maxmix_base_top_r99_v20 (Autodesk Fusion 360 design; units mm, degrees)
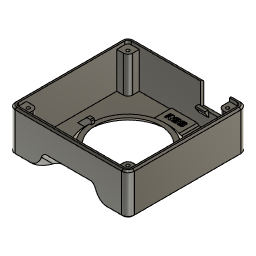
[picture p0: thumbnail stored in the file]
sketch "Sketch1" plane through (0, 0, 0) normal (0, 0, 1) x axis (1, 0, 0)
  line L1 (33, 37) -> (-33, 37)
  line L2 (37, -33) -> (37, 33)
  line L3 (-33, -37) -> (33, -37)
  line L4 (-37, 33) -> (-37, -33)
  line L5 (33, 35) -> (-33, 35)
  line L6 (35, -33) -> (35, 33)
  line L7 (-33, -35) -> (33, -35)
  line L8 (-35, 33) -> (-35, -33)
  line L9 (33, -33) -> (-33, 33)
  line L10 (-33, -33) -> (33, 33)
  arc A1 centre (-33, 33) radius 4 clockwise from (-37, 33) to (-33, 37)
  arc A2 centre (-33, -33) radius 4 clockwise from (-33, -37) to (-37, -33)
  arc A3 centre (33, -33) radius 4 clockwise from (37, -33) to (33, -37)
  arc A4 centre (33, 33) radius 4 clockwise from (33, 37) to (37, 33)
  arc A5 centre (-33, 33) radius 2 clockwise from (-35, 33) to (-33, 35)
  arc A6 centre (-33, -33) radius 2 clockwise from (-33, -35) to (-35, -33)
  arc A7 centre (33, -33) radius 2 clockwise from (35, -33) to (33, -35)
  arc A8 centre (33, 33) radius 2 clockwise from (33, 35) to (35, 33)
  point P15 (-33, 33)
  point P25 (-33, 33)
  point P21 (33, -33)
  point P26 (33, -33)
  point P12 (33, 33)
  point P27 (33, 33)
  point P6 (-33, -33)
  point P28 (-33, -33)
  point P3 (-33, 33)
  point P29 (0, 0)
  horizontal L1
  perpendicular L1 L2
  parallel L1 L3
  parallel L2 L4
  tangent L1 A1
  tangent L4 A1
  tangent L4 A2
  tangent L3 A2
  equal A1 A2
  tangent L3 A3
  tangent L2 A3
  equal A1 A3
  tangent L2 A4
  tangent L1 A4
  equal A1 A4
  horizontal L5
  vertical L6
  horizontal L7
  vertical L8
  tangent L5 A5
  tangent L8 A5
  tangent L8 A6
  tangent L7 A6
  equal A5 A6
  tangent L7 A7
  tangent L6 A7
  equal A5 A7
  tangent L6 A8
  tangent L5 A8
  equal A5 A8
  coincident P15 P25
  coincident P21 P26
  coincident P12 P27
  coincident P6 P28
  coincident P3 P15
  midpoint L9 L10
  midpoint L10 P29
  dimension "d3" radius A1 = 4
  dimension "d4" distance L2 L6 = 2
  dimension "d5" radius A5 = 2
  dimension "d6" distance L1 L3 = 74
  dimension "d7" distance L2 L4 = 74
extrude "Extrude1" new body sketch "Sketch1" profile of L1 L2 L3 L4 A1 A2 A3 A4 L5 L6 L7 L8 A5 A6 A7 A8 along normal blind 23.5
sketch "Sketch2" plane through (0, 0, 0) normal (0, 0, 1) x axis (1, 0, 0)
  line L1 (37, -33) -> (37, 33)
  line L2 (33, 37) -> (-33, 37)
  line L3 (-37, 33) -> (-37, -33)
  line L4 (-33, -37) -> (33, -37)
  arc A1 centre (33, -33) radius 4 clockwise from (37, -33) to (33, -37)
  arc A2 centre (33, 33) radius 4 clockwise from (33, 37) to (37, 33)
  arc A3 centre (-33, 33) radius 4 clockwise from (-37, 33) to (-33, 37)
  arc A4 centre (-33, -33) radius 4 clockwise from (-33, -37) to (-37, -33)
  circle C1 centre (0, 0) radius 24.1
  point P1 (0, 0)
  point P14 (0, 0)
  coincident P1 P14
  dimension "d10" diameter C1 = 48.2
extrude "Extrude2" add sketch "Sketch2" against normal blind 2
sketch "Sketch3" plane through (0, 0, 0) normal (1, 0, 0) x axis (0, 1, 0)
  line L1 (-37, 23.5) -> (-37, -2)
  line L2 (-33, -2) -> (-37, -2)
  line L3 (33, -2) -> (-33, -2)
  line L4 (-27.1005, -2) -> (-37, 7.8995)
  line L5 (-25.4034, -2) -> (-37, 9.5966)
  point P6 (-27.1005, -2)
  point P7 (-37, 7.8995)
  point P8 (-37, 9.5966)
  point P9 (-25.4034, -2)
  coincident L3 P6
  coincident L1 P7
  parallel L4 L5
  coincident L1 P8
  coincident L3 P9
  dimension "d15" distance L4 L5 = 1.2
  dimension "d27" distance P6 P7 = 14
  dimension "d28" angle L1 L4 = 45
extrude "Extrude3" add sketch "Sketch3" profile of L1 L3 L4 L5 along normal blind 19.3 and against normal blind 19
sketch "Sketch4" plane through (0, -14.5503, -14.5503) normal (0, -0.7071, -0.7071) x axis (1, 0, 0)
  line L1 (-19, 7.178) -> (-19, 52.7164)
  line L2 (19.3, 7.178) -> (-19, 7.178)
  line L3 (19.3, 52.7164) -> (19.3, 7.178)
  line L4 (-19, 52.7164) -> (19.3, 52.7164)
  point P6 (-19, 52.7164)
  point P10 (-19, 52.7164)
  point P4 (-19, 19.3772)
  point P2 (19.3, 30.1203)
  vertical L1
  perpendicular L1 L2
  perpendicular L2 L3
  perpendicular L3 L4
  coincident P6 P10
  coincident P4 L1
  coincident P2 L3
extrude "Extrude4" cut sketch "Sketch4" no distance stored
sketch "Sketch5" plane through (19.3, 0, 0) normal (-1, 0, 0) x axis (0, -1, 0)
  line L1 (35, 0) -> (35, 5.8995)
  line L2 (29.1005, 0) -> (35, 0)
  line L3 (27.1005, -2) -> (29.1005, 0)
  line L4 (37, -2) -> (27.1005, -2)
  line L5 (37, 7.8995) -> (37, -2)
  line L6 (35, 5.8995) -> (37, 7.8995)
  line L7 (37, -2) -> (27.1005, -2)
  line L8 (37, -2) -> (37, 7.8995)
  line L9 (27.1005, -2) -> (37, 7.8995)
  point P10 (27.1005, -2)
  point P11 (27.1005, -2)
  point P6 (37, -2)
  point P12 (37, -2)
  point P8 (37, 7.8995)
  point P13 (37, 7.8995)
  point P9 (37, -2)
  point P14 (37, -2)
  point P15 (37, 7.8995)
  point P16 (27.1005, -2)
  coincident P10 P11
  coincident P6 P12
  coincident P8 P13
  coincident P9 P14
  coincident P8 P15
  coincident P10 P16
extrude "Extrude5" add sketch "Sketch5" along normal blind 2.2
sketch "Sketch7" plane through (-19, 0, 0) normal (1, 0, 0) x axis (0, 1, 0)
  line L1 (-35, 5.8995) -> (-35, 0)
  line L2 (-37, 7.8995) -> (-35, 5.8995)
  line L3 (-37, -2) -> (-37, 7.8995)
  line L4 (-27.1005, -2) -> (-37, -2)
  line L5 (-29.1005, 0) -> (-27.1005, -2)
  line L6 (-35, 0) -> (-29.1005, 0)
  line L7 (-27.1005, -2) -> (-37, 7.8995)
  line L8 (-37, -2) -> (-27.1005, -2)
  line L9 (-37, 7.8995) -> (-37, -2)
  point P9 (-37, 7.8995)
  point P11 (-37, 7.8995)
  point P10 (-27.1005, -2)
  point P12 (-27.1005, -2)
  point P13 (-27.1005, -2)
  point P8 (-37, -2)
  point P14 (-37, -2)
  point P5 (-37, -2)
  point P15 (-37, -2)
  coincident P9 P11
  coincident P10 P12
  coincident P10 P13
  coincident P8 P14
  coincident P5 P15
extrude "Extrude8" add sketch "Sketch7" along normal blind 1.9
sketch "Sketch6" plane through (0, -13.7017, -13.7017) normal (0, 0.7071, 0.7071) x axis (-1, 0, 0)
  line L1 (19, 19.3772) -> (-19.3, 19.3772)
  line L2 (-19.3, 30.1203) -> (19, 30.1203)
  line L3 (-19.3, 19.3772) -> (-19.3, 30.1203)
  line L4 (19, 17.6203) -> (19, 19.3772)
  line L5 (-19.3, 17.6203) -> (19, 17.6203)
  line L6 (-19.3, 19.3772) -> (-19.3, 17.6203)
  line L7 (-19.3, 19.3772) -> (19, 19.3772)
  line L8 (11.5, 28.7483) -> (-11.5, 28.7483)
  line L9 (12.5, 21.7483) -> (12.5, 27.7483)
  line L10 (-11.5, 20.7483) -> (11.5, 20.7483)
  line L11 (-12.5, 27.7483) -> (-12.5, 21.7483)
  line L12 (-35, 39.9515) -> (-35, -6.7175)
  line L13 (35, -6.7175) -> (35, 39.9515)
  line L14 (19, 30.1203) -> (19, 19.3772)
  arc A1 centre (-11.5, 27.7483) radius 1 clockwise from (-12.5, 27.7483) to (-11.5, 28.7483)
  arc A2 centre (-11.5, 21.7483) radius 1 clockwise from (-11.5, 20.7483) to (-12.5, 21.7483)
  arc A3 centre (11.5, 21.7483) radius 1 clockwise from (12.5, 21.7483) to (11.5, 20.7483)
  arc A4 centre (11.5, 27.7483) radius 1 clockwise from (11.5, 28.7483) to (12.5, 27.7483)
  point P3 (19, 19.3772)
  point P10 (19, 19.3772)
  point P6 (-19.3, 19.3772)
  point P13 (-19.3, 19.3772)
  point P4 (19, 30.1203)
  point P9 (19, 30.1203)
  coincident P3 P10
  perpendicular L1 L4
  perpendicular L3 L5
  coincident P6 P13
  perpendicular L1 L6
  horizontal L8
  vertical L9
  horizontal L10
  vertical L11
  tangent L8 A1
  tangent L11 A1
  tangent L11 A2
  tangent L10 A2
  equal A1 A2
  tangent L10 A3
  tangent L9 A3
  equal A1 A3
  tangent L9 A4
  tangent L8 A4
  equal A1 A4
  dimension "d29" distance P4 L5 = 12.5
  dimension "d31" distance P9 L8 = 1.372
  dimension "d34" distance L9 L13 = 22.5
  dimension "d35" distance L11 L12 = 22.5 (= "d34")
  dimension "d36" distance L8 L10 = 8
  dimension "d37" radius A1 = 1
extrude "Extrude6" cut sketch "Sketch6" profile of L1 L4 L5 L6 L7 no distance stored
extrude "Extrude7" cut sketch "Sketch6" profile of L8 L9 L10 L11 A1 A2 A3 A4 no distance stored
sketch "Sketch8" plane through (0, 0, 0) normal (1, 0, 0) x axis (0, 1, 0)
  line L1 (-35, 23.5) -> (-35, 0)
  line L2 (-27.4034, 0) -> (-35, 7.5966)
  line L3 (-30.8988, 11.6978) -> (-35, 7.5966)
  line L4 (-35, 15.799) -> (-30.8988, 11.6978)
  point P4 (-35, 7.5966)
  point P6 (-35, 7.5966)
  point P8 (-35, 15.799)
  point P7 (-30.8988, 11.6978)
  coincident P4 P6
  perpendicular L2 L3
  perpendicular L3 L4
  coincident L1 P8
  dimension "d46" distance P6 P7 = 5.8
extrude "Extrude9" add sketch "Sketch8" profile of L1 L3 L4 along normal blind 3.26 (= "35 mm - 31.74 mm") and against normal blind 2.54 (= "35 mm - 32.46 mm")
sketch "Sketch9" plane through (0, -9.6005, -9.6005) normal (0, 0.7071, 0.7071) x axis (-1, 0, 0)
  line L1 (-3.26, 30.1203) -> (-3.26, 35.9203)
  line L2 (2.54, 30.1203) -> (-3.26, 30.1203)
  line L3 (2.54, 35.9203) -> (2.54, 30.1203)
  line L4 (-2.26, 33.9203) -> (-2.26, 30.1203)
  line L5 (1.54, 33.9203) -> (-2.26, 33.9203)
  line L6 (1.54, 30.1203) -> (1.54, 33.9203)
  line L7 (-3.26, 35.9203) -> (2.54, 35.9203)
  line L8 (-0.36, 31.5203) -> (-0.36, 30.1203)
  circle C1 centre (-0.36, 31.5203) radius 0.925
  point P6 (-2.26, 30.1203)
  point P9 (1.54, 30.1203)
  point P10 (-0.36, 30.1203)
  point P11 (-0.36, 31.5203)
  point P12 (-0.36, 31.5203)
  coincident L2 P6
  perpendicular L2 L4
  perpendicular L4 L5
  coincident L2 P9
  perpendicular L2 L6
  midpoint L2 P10
  perpendicular L2 L8
  coincident P11 P12
  dimension "d52" distance L2 L5 = 3.8
  dimension "d53" distance L3 L6 = 1
  dimension "d54" distance L1 L4 = 1 (= "d53")
  dimension "d55" distance P10 P11 = 1.4
  dimension "d56" diameter C1 = 1.85
extrude "Extrude10" cut sketch "Sketch9" profile of L2 L4 L5 L6 C1 against normal blind 2
extrude "Extrude11" cut sketch "Sketch9" profile of C1 against normal blind 5
sketch "Sketch10" plane through (19.3, 0, 0) normal (1, 0, 0) x axis (0, 1, 0)
  line L1 (-27.4034, 0) -> (-35, 0)
  line L2 (-35, 7.5966) -> (-27.4034, 0)
  line L3 (-35, 0) -> (-35, 7.5966)
  line L4 (-27.4034, 0) -> (-35, 7.5966)
  line L5 (-35, 23.5) -> (-35, 0)
  line L6 (33, 0) -> (-33, 0)
  line L7 (-33, 0) -> (-35, 0)
  line L8 (-22.4537, 0) -> (-35, 12.5463)
  point P11 (-35, 12.5463)
  point P12 (-22.4537, 0)
  coincident L5 P11
  coincident L6 P12
  parallel L2 L8
  dimension "d61" distance L4 L8 = 3.5
extrude "Extrude12" add sketch "Sketch10" profile of L1 L2 L3 L5 L6 L7 L8 along normal blind 1.2
extrude "Extrude13" sketch "Sketch10" profile of L1 L2 L3 L5 L6 L7 L8 blind -1.5
sketch "Sketch24" plane through (-20.5, 0, 0) normal (-1, 0, 0) x axis (0, -1, 0)
  line L1 (22.4537, 0) -> (35, 12.5463)
  line L2 (35, 0) -> (22.4537, 0)
  line L3 (35, 12.5463) -> (35, 0)
  line L4 (22.4537, 0) -> (35, 12.5463)
  line L5 (29.7269, 5.2731) -> (28.7269, 6.2731)
  line L6 (29.7269, 7.2731) -> (29.7269, 5.2731)
  line L7 (27.7269, 5.2731) -> (29.7269, 5.2731)
  point P2 (35, 12.5463)
  point P7 (35, 12.5463)
  point P6 (22.4537, 0)
  point P8 (22.4537, 0)
  point P9 (28.7269, 6.2731)
  point P11 (29.7269, 7.2731)
  point P12 (27.7269, 5.2731)
  point P10 (29.7269, 5.2731)
  coincident P2 P7
  coincident P6 P8
  midpoint L4 P9
  perpendicular L4 L5
  coincident L4 P11
  perpendicular L2 L6
  coincident L4 P12
  perpendicular L6 L7
  dimension "d155" distance P10 P11 = 2
extrude "Extrude25" cut sketch "Sketch24" profile of L1 L4 L6 L7 to an object
sketch "Sketch12" plane through (0, 0, 0) normal (1, 0, 0) x axis (0, 1, 0)
  line L1 (-24.1, -2) -> (24.1, -2)
  line L2 (24.1, 0) -> (-24.1, 0)
  line L3 (0, 2) -> (0, -2)
  line L4 (-20.1, 2) -> (0, 2)
  line L5 (-20.1, 2) -> (-24.1, -2)
  line L6 (-22.9189, 2) -> (-20.1, 2)
  line L7 (-24.9189, 0) -> (-26.1612, -1.2423)
  line L8 (-24.9189, 0) -> (-22.9189, 2)
  line L9 (-24.1, 0) -> (-24.1, -2)
  line L10 (-24.9189, 0) -> (-24.1, 0)
  point P6 (0, -2)
  point P3 (-24.1, -2)
  point P9 (-24.1, -2)
  point P12 (-24.9189, 0)
  point P13 (-24.9189, 0)
  point P4 (-24.1, 0)
  point P14 (-24.1, 0)
  point P7 (0, 2)
  point P8 (-20.1, 2)
  midpoint L1 P6
  perpendicular L2 L3
  perpendicular L3 L4
  coincident P3 P9
  parallel L4 L6
  coincident P12 P13
  parallel L5 L8
  coincident P4 P14
  dimension "d70" distance P6 P7 = 4
  dimension "d71" distance P7 P8 = 20.1 (= "( 40.2 / 2 ) * 1 mm")
revolve "Revolve1" sketch "Sketch12" AlongAngle 360
work_plane "WorkPlane1" AlongDistance 11.2
sketch "Sketch13" plane through (11.2, 0, 0) normal (1, 0, 0) x axis (0, 1, 0)
  line L1 (-35, 7.5966) -> (-26.1612, -1.2423)
  line L2 (-24.2308, 0.6881) -> (-25.1146, 1.572)
  line L3 (-24.9189, 0) -> (-26.1612, -1.2423)
  line L4 (-24.2308, 0.6881) -> (-24.9189, 0)
  line L5 (-24.9189, 0) -> (-22.4537, 0)
  line L6 (24.9189, 0) -> (-24.9189, 0)
  line L7 (-22.4537, 0) -> (-24.9189, 0)
  line L8 (-35, 0) -> (-22.4537, 0)
  line L9 (-33, 0) -> (-35, 0)
  line L10 (33, 0) -> (-33, 0)
  line L11 (35, 0) -> (33, 0)
  line L12 (35, 0) -> (33, 0)
  line L13 (-33, 0) -> (33, 0)
  line L14 (-33, 0) -> (-35, 0)
  line L15 (-22.4537, 0) -> (-35, 0)
  line L16 (-24.2308, 0) -> (-24.2308, 0.6881)
  line L17 (-23.8419, 2.8448) -> (-25.1146, 1.572)
  line L18 (-20.9971, 0) -> (-23.8419, 2.8448)
  point P5 (-24.9189, 0)
  point P6 (-24.9189, 0)
  point P15 (-24.2308, 0)
  point P17 (-20.9971, 0)
  point P4 (-25.1146, 1.572)
  point P16 (-23.8419, 2.8448)
  point P7 (-24.2308, 0.6881)
  parallel L1 L2
  coincident P5 P6
  perpendicular L2 L4
  coincident L8 P15
  vertical L16
  perpendicular L2 L17
  coincident L13 P17
  parallel L2 L18
  dimension "d75" distance L1 L2 = 2.73
  dimension "d76" distance P4 P16 = 1.8
  dimension "d77" distance P4 P7 = 1.25
extrude "Extrude14" add sketch "Sketch13" profile of L2 L5 L6 L7 L8 L10 L13 L15 L16 L17 L18 along normal blind 4
mirror "Mirror2" mirrorStitchTolerance 0.1
chamfer "Chamfer7" distance 0.75
sketch "Sketch14" plane through (0, 0, 0) normal (0, 1, 0) x axis (1, 0, 0)
  line L1 (22.9189, -2) -> (-22.9189, -2)
  line L2 (-24.9189, 0) -> (24.9189, 0)
  line L3 (20.5, 0) -> (33, 0)
  line L4 (20.1, -2) -> (-20.1, -2)
  line L5 (24.6, -4.6) -> (29.2, 0)
  line L6 (22.4, -4.6) -> (24.6, -4.6)
  line L7 (21.8, -2) -> (21.8, -4)
  line L8 (22.9189, -2) -> (24.9189, 0)
  line L9 (23.8, 0) -> (21.8, -2)
  line L10 (21.8, -4) -> (22.4, -4.6)
  point P10 (29.2, 0)
  point P12 (21.8, -2)
  point P4 (24.9189, 0)
  point P13 (24.9189, 0)
  point P3 (22.9189, -2)
  point P14 (22.9189, -2)
  point P15 (23.8, 0)
  point P1 (0, 0)
  point P11 (24.6, -4.6)
  point P17 (21.8, -4)
  coincident L3 P10
  parallel L3 L6
  coincident L1 P12
  perpendicular L1 L7
  coincident P4 P13
  coincident P3 P14
  parallel L5 L8
  coincident L3 P15
  parallel L5 L9
  dimension "d82" distance L1 L6 = 2.6
  dimension "d83" distance P1 L7 = 21.8 (= "( 43.6 / 2 ) * 1 mm")
  dimension "d87" distance P11 L7 = 2.8
  dimension "d88" angle L6 L10 = 45
  dimension "d89" distance L6 P17 = 0.6
extrude "Extrude15" add sketch "Sketch14" profile of L2 L3 L5 L6 L7 L9 distance 2
mirror "Mirror3" mirrorStitchTolerance 0.1
sketch "Sketch15" plane through (0, 0, 0) normal (0, 0, 1) x axis (-1, 0, 0)
  line L1 (24.8988, -1) -> (29.2, -1)
  line L2 (-29.2, -1) -> (-24.8988, -1)
  line L3 (-29.2, 1) -> (-29.2, -1)
  line L4 (-24.8988, 1) -> (-29.2, 1)
  line L5 (-15.2, 20.9971) -> (-13.4192, 20.9971)
  line L6 (-15.2, 24.2308) -> (-15.2, 20.9971)
  line L7 (-11.2, 24.2308) -> (-15.2, 24.2308)
  line L8 (-11.2, 22.2601) -> (-11.2, 24.2308)
  line L9 (-19.3, 24.9189) -> (0, 24.9189)
  line L10 (-19.3, 22.4537) -> (-19.3, 24.9189)
  line L11 (-20.5, 22.4537) -> (-19.3, 22.4537)
  line L12 (-20.5, 35) -> (-20.5, 22.4537)
  line L13 (-33, 35) -> (-20.5, 35)
  line L14 (-35, -33) -> (-35, 33)
  line L15 (33, -35) -> (-33, -35)
  line L16 (35, 33) -> (35, -33)
  line L17 (19, 24.9189) -> (19, 22.4537)
  line L18 (19, 22.4537) -> (20.5, 22.4537)
  line L19 (20.5, 22.4537) -> (20.5, 35)
  line L20 (11.2, 24.2308) -> (11.2, 22.2601)
  line L21 (15.2, 24.2308) -> (11.2, 24.2308)
  line L22 (15.2, 20.9971) -> (15.2, 24.2308)
  line L23 (13.4192, 20.9971) -> (15.2, 20.9971)
  line L24 (29.2, 1) -> (24.8988, 1)
  line L25 (29.2, -1) -> (29.2, 1)
  line L26 (35, -33) -> (35, 33)
  line L27 (-33, -35) -> (33, -35)
  line L28 (0, 0) -> (33, -33)
  line L29 (28, -35) -> (28, -30.9)
  line L30 (35, -28) -> (30.9, -28)
  line L31 (20.5, 35) -> (33, 35)
  line L32 (0, 24.9189) -> (19, 24.9189)
  arc A1 centre (0, 0) radius 24.9189 clockwise from (24.8988, -1) to (-24.8988, -1)
  arc A2 centre (0, 0) radius 24.9189 clockwise from (-24.8988, 1) to (-13.4192, 20.9971)
  arc A3 centre (0, 0) radius 24.9189 clockwise from (-11.2, 22.2601) to (0, 24.9189)
  arc A4 centre (-33, 33) radius 2 clockwise from (-35, 33) to (-33, 35)
  arc A5 centre (-33, -33) radius 2 clockwise from (-33, -35) to (-35, -33)
  arc A6 centre (33, -33) radius 2 clockwise from (35, -33) to (33, -35)
  arc A7 centre (33, 33) radius 2 clockwise from (33, 35) to (35, 33)
  arc A8 centre (0, 0) radius 24.9189 clockwise from (0, 24.9189) to (11.2, 22.2601)
  arc A9 centre (0, 0) radius 24.9189 clockwise from (13.4192, 20.9971) to (24.8988, 1)
  arc A10 centre (33, -33) radius 2 clockwise from (35, -33) to (33, -35)
  circle C1 centre (30.9, -30.9) radius 1
  arc A11 centre (30.9, -30.9) radius 2.9 clockwise from (28, -30.9) to (30.9, -28)
  point P45 (33, -33)
  point P48 (33, -33)
  point P1 (0, 0)
  point P49 (0, 0)
  point P50 (30.9, -30.9)
  point P51 (30.9, -30.9)
  point P54 (28, -35)
  point P55 (35, -28)
  coincident P45 P48
  coincident P1 P49
  coincident L28 P50
  coincident L28 P51
  coincident P50 P51
  tangent L29 A11
  tangent L30 A11
  coincident L15 P54
  coincident L16 P55
  vertical L29
  horizontal L30
  dimension "d92" distance P1 P51 = 30.9
  dimension "d93" diameter C1 = 2
  dimension "d94" diameter A11 = 5.8
extrude "Extrude16" add sketch "Sketch15" profile of L15 A6 L16 A10 L26 L27 A11 C1 L29 L30 along normal blind 21.5
circular_pattern "C-Pattern1" TotalAngle 360
sketch "Sketch16" plane through (0, 37, 0) normal (0, 1, 0) x axis (-1, 0, 0)
  line L1 (33, 23.5) -> (33, -2)
  line L2 (-33, 23.5) -> (33, 23.5)
  line L3 (-33, -2) -> (-33, 23.5)
  line L4 (33, -2) -> (-33, -2)
  line L5 (-37, 23.5) -> (-37, -2)
  line L6 (-28, 9.5) -> (-28, 23.5)
  line L7 (-10, 9.5) -> (-28, 9.5)
  line L8 (-10, 23.5) -> (-10, 9.5)
  point P8 (-28, 23.5)
  point P11 (-10, 23.5)
  point P9 (-28, 9.5)
  point P10 (-10, 9.5)
  coincident L2 P8
  perpendicular L2 L6
  perpendicular L6 L7
  coincident L2 P11
  perpendicular L2 L8
  dimension "d99" distance L5 L6 = 9
  dimension "d100" distance L2 L7 = 14
  dimension "d101" distance P9 P10 = 18
extrude "Extrude17" cut sketch "Sketch16" profile of L2 L6 L7 L8 to an object
work_plane "WorkPlane2"
sketch "Sketch18" plane through (19, 36, 16.5) normal (-1, 0, 0) x axis (0, 1, 0)
  line L1 (-1, 7) -> (1, 7)
  line L2 (-1.25, 7) -> (-1, 7)
  line L3 (-1.25, 6) -> (-1.25, 7)
  line L4 (-3.25, 6) -> (-1.25, 6)
  line L5 (-3.25, 7) -> (-3.25, 6)
  line L6 (-1, 10.2133) -> (-3.25, 7)
  line L7 (-1, -5) -> (-1, -7)
  line L8 (-1, 7) -> (-1, 16.5)
  point P3 (-1, 7)
  point P4 (-1, 7)
  point P8 (-3.25, 7)
  point P9 (-1, 10.2133)
  point P6 (-1.25, 6)
  point P7 (-3.25, 6)
  coincident P3 P4
  perpendicular L2 L3
  perpendicular L2 L5
  coincident L2 P8
  horizontal L4
  vertical L3
  coincident P9 L8
  dimension "d115" distance P4 L3 = 0.25
  dimension "d116" distance P6 P7 = 2
  dimension "d118" distance P7 P8 = 1
  dimension "d158" angle L6 L8 = 35
extrude "Extrude19" sketch "Sketch18" profile of L2 L3 L4 L5 L6 blind 5
mirror "Mirror4" mirrorStitchTolerance 0.1
sketch "Sketch20" plane through (10, 0, 0) normal (-1, 0, 0) x axis (0, -1, 0)
  line L1 (-34.75, 10.5) -> (-32.75, 10.5)
  line L2 (-34.75, 9.5) -> (-34.75, 10.5)
  line L3 (-35, 9.5) -> (-34.75, 9.5)
  line L4 (-35, 6.2867) -> (-35, 9.5)
  line L5 (-32.75, 9.5) -> (-35, 6.2867)
  line L6 (-32.75, 10.5) -> (-32.75, 9.5)
  line L7 (-35, 6.2867) -> (-35, 9.5)
  line L8 (-35, 10.5) -> (-35, 9.5)
  line L9 (-32.75, 10.5) -> (-35, 10.5)
  line L10 (-32.75, 9.5) -> (-32.75, 10.5)
  line L11 (-35, 6.2867) -> (-32.75, 9.5)
  point P11 (-35, 9.5)
  point P13 (-35, 9.5)
  point P10 (-32.75, 10.5)
  point P15 (-32.75, 10.5)
  point P16 (-32.75, 10.5)
  point P9 (-32.75, 9.5)
  point P17 (-32.75, 9.5)
  point P12 (-35, 6.2867)
  point P18 (-35, 6.2867)
  coincident P11 P13
  perpendicular L1 L8
  coincident P10 P15
  perpendicular L6 L9
  coincident P10 P16
  coincident P9 P17
  coincident P12 P18
extrude "Extrude21" add sketch "Sketch20" along normal blind 1
chamfer "Chamfer3" distance 1
chamfer "Chamfer4" distance 1
fillet "Fillet5" radius 3.5
fillet "Fillet6" radius 8
sketch "Sketch25" plane through (0, 0, 0) normal (0, 0, 1) x axis (-1, 0, 0)
  line L1 (-30.9, -28) -> (-35, -28)
  line L2 (-28, -35) -> (-28, -30.9)
  line L3 (28, -35) -> (-28, -35)
  line L4 (28, -30.9) -> (28, -35)
  line L5 (35, -28) -> (30.9, -28)
  line L6 (35, 28) -> (35, -28)
  line L7 (30.9, 28) -> (35, 28)
  line L8 (28, 35) -> (28, 30.9)
  line L9 (20.5, 35) -> (28, 35)
  line L10 (20.5, 22.4537) -> (20.5, 35)
  line L11 (19, 22.4537) -> (20.5, 22.4537)
  line L12 (19, 24.9189) -> (19, 22.4537)
  line L13 (0, 24.9189) -> (19, 24.9189)
  line L14 (11.2, 24.2308) -> (11.2, 22.2601)
  line L15 (15.2, 24.2308) -> (11.2, 24.2308)
  line L16 (15.2, 20.9971) -> (15.2, 24.2308)
  line L17 (13.4192, 20.9971) -> (15.2, 20.9971)
  line L18 (29.2, 1) -> (24.8988, 1)
  line L19 (29.2, -1) -> (29.2, 1)
  line L20 (24.8988, -1) -> (29.2, -1)
  line L21 (-29.2, -1) -> (-24.8988, -1)
  line L22 (-29.2, 1) -> (-29.2, -1)
  line L23 (-24.8988, 1) -> (-29.2, 1)
  line L24 (-15.2, 20.9971) -> (-13.4192, 20.9971)
  line L25 (-15.2, 24.2308) -> (-15.2, 20.9971)
  line L26 (-11.2, 24.2308) -> (-15.2, 24.2308)
  line L27 (-11.2, 22.2601) -> (-11.2, 24.2308)
  line L28 (-19.3, 24.9189) -> (0, 24.9189)
  line L29 (-19.3, 22.4537) -> (-19.3, 24.9189)
  line L30 (-20.5, 22.4537) -> (-19.3, 22.4537)
  line L31 (-20.5, 35) -> (-20.5, 22.4537)
  line L32 (-28, 35) -> (-20.5, 35)
  line L33 (-28, 30.9) -> (-28, 35)
  line L34 (-35, 28) -> (-30.9, 28)
  line L35 (-35, -28) -> (-35, 28)
  line L36 (0, -35) -> (0, 0)
  line L37 (8, -23.5998) -> (8, -35)
  line L38 (-8, -35) -> (-8, -23.5998)
  line L39 (-35, 15) -> (-19.8985, 15)
  line L40 (35, 15) -> (19.8985, 15)
  arc A1 centre (-30.9, -30.9) radius 2.9 clockwise from (-30.9, -28) to (-28, -30.9)
  arc A2 centre (30.9, -30.9) radius 2.9 clockwise from (28, -30.9) to (30.9, -28)
  arc A3 centre (30.9, 30.9) radius 2.9 clockwise from (30.9, 28) to (28, 30.9)
  arc A4 centre (0, 0) radius 24.9189 clockwise from (0, 24.9189) to (11.2, 22.2601)
  arc A5 centre (0, 0) radius 24.9189 clockwise from (13.4192, 20.9971) to (24.8988, 1)
  arc A6 centre (0, 0) radius 24.9189 clockwise from (24.8988, -1) to (-24.8988, -1)
  arc A7 centre (0, 0) radius 24.9189 clockwise from (-24.8988, 1) to (-13.4192, 20.9971)
  arc A8 centre (0, 0) radius 24.9189 clockwise from (-11.2, 22.2601) to (0, 24.9189)
  arc A9 centre (-30.9, 30.9) radius 2.9 clockwise from (-28, 30.9) to (-30.9, 28)
  arc A10 centre (0, 0) radius 24.9189 clockwise from (24.8988, -1) to (-24.8988, -1)
  point P52 (0, 0)
  point P53 (0, 0)
  point P54 (0, -35)
  point P55 (8, -35)
  point P56 (8, -23.5998)
  point P57 (-8, -23.5998)
  point P58 (-8, -35)
  point P59 (-19.8985, 15)
  point P60 (-35, 15)
  point P61 (19.8985, 15)
  point P62 (35, 15)
  point P1 (0, 0)
  coincident P52 P53
  midpoint L3 P54
  coincident L3 P55
  coincident A6 P56
  perpendicular L3 L37
  coincident A6 P57
  coincident L3 P58
  perpendicular L3 L38
  symmetric L36 L37 L38
  coincident A7 P59
  coincident L35 P60
  perpendicular L35 L39
  coincident A5 P61
  coincident L6 P62
  perpendicular L6 L40
  collinear L39 L40
  dimension "d159" distance L37 L38 = 16
  dimension "d160" distance P1 L39 = 15
extrude "Extrude26" cut sketch "Sketch25" profile of L1 A1 L2 L3 L4 A2 L5 L6 A5 L18 L19 L20 A6 L21 L22 L23 A7 L35 A10 L37 L38 L39 L40 against normal blind 1
delete_face "DeleteFace1"
chamfer "Chamfer8" distance 1
sketch "Sketch17" plane through (0, 0, -2) normal (0, 0, -1) x axis (1, 0, 0)
  line L1 (-13.6, 27.1005) -> (13.6, 27.1005)
  line L2 (-33, 36) -> (-23.8536, 36)
  line L3 (-36, -33) -> (-36, 33)
  line L4 (33, -36) -> (-33, -36)
  line L5 (36, 33) -> (36, -33)
  line L6 (23.8536, 36) -> (33, 36)
  line L7 (-31.4268, 33) -> (-25.4268, 33)
  line L8 (-31.4268, 27) -> (-31.4268, 33)
  line L9 (-28.4268, 29.2) -> (-31.4268, 27)
  line L10 (-25.4268, 27) -> (-28.4268, 29.2)
  line L11 (-25.4268, 33) -> (-25.4268, 27)
  line L12 (-28.4268, 29.2) -> (-28.4268, 33)
  line L13 (-23.8536, 36) -> (-33, 36)
  line L14 (-36, 33) -> (-36, -33)
  line L15 (-28.4268, 33) -> (-28.4268, 36)
  circle C1 centre (0, 0) radius 24.1
  closed curve K1 centre (23.8536, 24.6863)
  closed curve K2 centre (13.6, 32.0503)
  closed curve K3 centre (-13.6, 32.0503)
  closed curve K4 centre (-23.8536, 24.6863)
  arc A1 centre (-33, 33) radius 3 clockwise from (-36, 33) to (-33, 36)
  arc A2 centre (-33, -33) radius 3 clockwise from (-33, -36) to (-36, -33)
  arc A3 centre (33, -33) radius 3 clockwise from (36, -33) to (33, -36)
  arc A4 centre (33, 33) radius 3 clockwise from (33, 36) to (36, 33)
  point P30 (-28.4268, 33)
  point P28 (-28.4268, 29.2)
  point P31 (-28.4268, 29.2)
  point P36 (-28.4268, 36)
  point P25 (-25.4268, 33)
  point P26 (-31.4268, 33)
  point P27 (-31.4268, 27)
  horizontal L7
  perpendicular L7 L11
  vertical L8
  equal L7 L11
  equal L8 L11
  midpoint L7 P30
  perpendicular L7 L12
  coincident P28 P31
  midpoint L2 P36
  vertical L15
  dimension "d108" distance P25 P26 = 6
  dimension "d109" distance P27 P31 = 2.2
  dimension "d110" distance L2 L7 = 3
extrude "Extrude18" cut sketch "Sketch17" profile of L7 L8 L9 L10 L11 against normal blind 1
sketch "Sketch23" plane through (0, 0, 0) normal (0, 0, 1) x axis (-1, 0, 0)
  line L1 (35, 28) -> (35, 15)
  line L2 (30.9, 28) -> (35, 28)
  line L3 (28, 35) -> (28, 30.9)
  line L4 (20.5, 35) -> (28, 35)
  line L5 (20.5, 22.4537) -> (20.5, 35)
  line L6 (19, 22.4537) -> (20.5, 22.4537)
  line L7 (19, 24.9189) -> (19, 22.4537)
  line L8 (0, 24.9189) -> (19, 24.9189)
  line L9 (11.2, 24.2308) -> (11.2, 22.2601)
  line L10 (15.2, 24.2308) -> (11.2, 24.2308)
  line L11 (15.2, 20.9971) -> (15.2, 24.2308)
  line L12 (13.4192, 20.9971) -> (15.2, 20.9971)
  line L13 (-15.2, 20.9971) -> (-13.4192, 20.9971)
  line L14 (-15.2, 24.2308) -> (-15.2, 20.9971)
  line L15 (-11.2, 24.2308) -> (-15.2, 24.2308)
  line L16 (-11.2, 22.2601) -> (-11.2, 24.2308)
  line L17 (-19.3, 24.9189) -> (0, 24.9189)
  line L18 (-19.3, 22.4537) -> (-19.3, 24.9189)
  line L19 (-20.5, 22.4537) -> (-19.3, 22.4537)
  line L20 (-20.5, 35) -> (-20.5, 22.4537)
  line L21 (-28, 35) -> (-20.5, 35)
  line L22 (-28, 30.9) -> (-28, 35)
  line L23 (-35, 28) -> (-30.9, 28)
  line L24 (-35, 15) -> (-35, 28)
  curve K1 (-5.4416, -27.9761) -> (5.4656, -27.9761)
  curve K2 (-5.4416, -33.9761) -> (-5.4416, -27.9761)
  curve K3 (5.4656, -33.9761) -> (-5.4416, -33.9761)
  curve K4 (5.4656, -27.9761) -> (5.4656, -33.9761)
  line L25 (-33, -35) -> (-28, -35)
  line L26 (0, -35) -> (0, 0)
  line L27 (-19.8985, 15) -> (-35, 15)
  line L28 (35, 15) -> (19.8985, 15)
  arc A1 centre (30.9, 30.9) radius 2.9 clockwise from (30.9, 28) to (28, 30.9)
  arc A2 centre (0, 0) radius 24.9189 clockwise from (-19.8985, 15) to (-13.4192, 20.9971)
  arc A3 centre (0, 0) radius 24.9189 clockwise from (13.4192, 20.9971) to (19.8985, 15)
  arc A4 centre (0, 0) radius 24.9189 clockwise from (-11.2, 22.2601) to (0, 24.9189)
  arc A5 centre (-30.9, 30.9) radius 2.9 clockwise from (-28, 30.9) to (-30.9, 28)
  arc A6 centre (0, 0) radius 24.9189 clockwise from (0, 24.9189) to (11.2, 22.2601)
  point P15 (0, 0)
  point P41 (0, 0)
  perpendicular K1 K2
  parallel K1 K3
  parallel K2 K4
  coincident P15 P41
extrude "Extrude24" cut sketch "Sketch23" against normal blind 0.4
